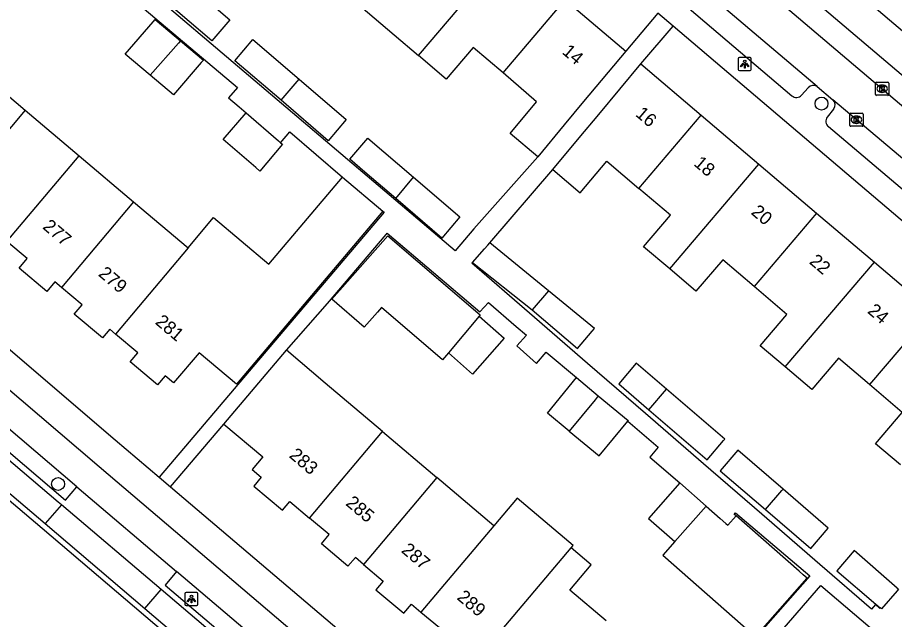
# Model space of a CAD drawing. Extents: x 162532 to 163264, y 381233 to 382042.
# Drawn here: x 162789.7 to 162856.2, y 381584 to 381629.7 of the extents above; entities that cross this region are included whole.
import ezdxf

# ---------------------------------------------------------------- set-up
doc = ezdxf.new("R2010")
doc.units = 0
for name, color, linetype in [('IMGEO_Berm_open', 7, 'Continuous'), ('IMGEO_Boom', 7, 'Continuous'), ('IMGEO_Fietspad_gesloten', 7, 'Continuous'), ('IMGEO_Kolk', 7, 'Continuous'), ('IMGEO_Lichtpunt', 7, 'Continuous'), ('IMGEO_Pand', 7, 'Continuous'), ('IMGEO_Pand_nummerreeks', 7, 'Continuous'), ('IMGEO_Parkeervlak_open', 7, 'Continuous'), ('IMGEO_Rijbaan_lokaal_gesloten', 7, 'Continuous'), ('IMGEO_Rijbaan_lokaal_open', 7, 'Continuous'), ('IMGEO_Voetpad_open', 7, 'Continuous')]:
    doc.layers.add(name, color=color, linetype=linetype)

msp = doc.modelspace()

# ---------------------------------------------------------------- linework, layer by layer
at = {"layer": 'IMGEO_Berm_open'}
for points in [[(162786.69, 381600.434), (162785.841, 381599.426), (162793.281, 381593.086), (162794.151, 381594.096)], [(162800.545, 381586.298), (162792.987, 381592.725)], [(162801.723, 381587.664), (162800.86, 381586.645), (162808.724, 381579.951), (162809.609, 381580.965)]]:
    msp.add_lwpolyline(points, dxfattribs=at)
at = {"layer": 'IMGEO_Boom'}
for centre in [(162850.632, 381623.161), (162792.731, 381594.303)]:
    msp.add_circle(centre, 0.489, dxfattribs=at)
at = {"layer": 'IMGEO_Fietspad_gesloten'}
for points in [[(162862.139, 381539.717), (162835.26, 381562.126), (162827.852, 381568.349), (162795.857, 381595.619), (162764.671, 381622.232), (162735.085, 381647.652), (162710.008, 381669.138)], [(162794.151, 381594.096), (162786.69, 381600.434)], [(162794.151, 381594.096), (162801.723, 381587.664)], [(162809.609, 381580.965), (162801.723, 381587.664)]]:
    msp.add_lwpolyline(points, dxfattribs=at)
at = {"layer": 'IMGEO_Kolk'}
for p, q in [((162854.728, 381623.861), (162854.728, 381624.713)), ((162854.803, 381624.787), (162855.655, 381624.787)), ((162855.216, 381624.567), (162855.241, 381624.567)), ((162855.729, 381624.713), (162855.729, 381623.861)), ((162855.655, 381623.787), (162854.803, 381623.787)), ((162855.239, 381624.007), (162855.214, 381624.007)), ((162852.777, 381621.51), (162852.777, 381622.362)), ((162852.852, 381622.436), (162853.704, 381622.436)), ((162853.265, 381622.216), (162853.29, 381622.216)), ((162853.778, 381622.362), (162853.778, 381621.51)), ((162853.288, 381621.656), (162853.263, 381621.656)), ((162853.704, 381621.436), (162852.852, 381621.436))]:
    msp.add_line(p, q, dxfattribs=at)
for points in [[(162854.728, 381623.861), (162854.728, 381624.713)], [(162854.803, 381624.787), (162855.655, 381624.787)], [(162855.049, 381624.487), (162855.172, 381624.487), (162855.172, 381624.336), (162855.302, 381624.487), (162855.466, 381624.487), (162855.32, 381624.336), (162855.473, 381624.087), (162855.321, 381624.087), (162855.236, 381624.251), (162855.172, 381624.184), (162855.172, 381624.087), (162855.049, 381624.087), (162855.049, 381624.487)], [(162855.729, 381624.713), (162855.729, 381623.861)], [(162855.655, 381623.787), (162854.803, 381623.787)], [(162852.777, 381621.51), (162852.777, 381622.362)], [(162852.852, 381622.436), (162853.704, 381622.436)], [(162853.778, 381622.362), (162853.778, 381621.51)], [(162853.098, 381622.136), (162853.221, 381622.136), (162853.221, 381621.985), (162853.351, 381622.136), (162853.515, 381622.136), (162853.369, 381621.985), (162853.522, 381621.736), (162853.37, 381621.736), (162853.285, 381621.9), (162853.221, 381621.833), (162853.221, 381621.736), (162853.098, 381621.736), (162853.098, 381622.136)], [(162853.704, 381621.436), (162852.852, 381621.436)]]:
    msp.add_lwpolyline(points, dxfattribs=at)
for centre, start, end in [((162854.805, 381624.711), 91.55205, 178.44795), ((162854.805, 381624.711), 91.55205, 178.44795), ((162855.653, 381624.711), 1.55205, 88.44795), ((162855.653, 381624.711), 1.55205, 88.44795), ((162854.805, 381623.863), 181.55205, 268.44795), ((162854.805, 381623.863), 181.55205, 268.44795), ((162855.653, 381623.863), 271.55205, 358.44795), ((162855.653, 381623.863), 271.55205, 358.44795), ((162852.854, 381622.36), 91.55205, 178.44795), ((162852.854, 381622.36), 91.55205, 178.44795), ((162853.702, 381622.36), 1.55205, 88.44795), ((162853.702, 381622.36), 1.55205, 88.44795), ((162852.854, 381621.512), 181.55205, 268.44795), ((162852.854, 381621.512), 181.55205, 268.44795), ((162853.702, 381621.512), 271.55205, 358.44795), ((162853.702, 381621.512), 271.55205, 358.44795)]:
    msp.add_arc(centre, 0.0765, start, end, dxfattribs=at)
for centre, major_axis, ratio, start_param, end_param in [((162855.215, 381624.287), (-0.387, 0.002), 0.722429, 4.712389, 7.853982), ((162855.24, 381624.287), (-0.39, 0.002), 0.717154, 1.570796, 4.712389), ((162853.264, 381621.936), (-0.387, 0.002), 0.722429, 4.712389, 7.853982), ((162853.289, 381621.936), (-0.39, 0.002), 0.717154, 1.570796, 4.712389)]:
    msp.add_ellipse(centre, major_axis=major_axis, ratio=ratio, start_param=start_param, end_param=end_param, dxfattribs=at)
at = {"layer": 'IMGEO_Lichtpunt'}
for p, q in [((162844.309, 381626.565), (162844.309, 381625.758)), ((162844.309, 381626.565), (162844.309, 381625.758)), ((162845.211, 381626.66), (162844.403, 381626.66)), ((162845.211, 381626.66), (162844.403, 381626.66)), ((162845.305, 381625.758), (162845.305, 381626.565)), ((162845.305, 381625.758), (162845.305, 381626.565)), ((162844.403, 381625.664), (162845.211, 381625.664)), ((162844.403, 381625.664), (162845.211, 381625.664)), ((162802.344, 381585.986), (162802.344, 381585.179)), ((162802.344, 381585.986), (162802.344, 381585.179)), ((162803.246, 381586.081), (162802.438, 381586.081)), ((162803.246, 381586.081), (162802.438, 381586.081)), ((162803.34, 381585.179), (162803.34, 381585.986)), ((162803.34, 381585.179), (162803.34, 381585.986)), ((162802.438, 381585.085), (162803.246, 381585.085)), ((162802.438, 381585.085), (162803.246, 381585.085))]:
    msp.add_line(p, q, dxfattribs=at)
for points in [[(162844.683, 381626.229), (162844.722, 381626.201), (162844.534, 381625.939), (162844.496, 381625.966), (162844.683, 381626.229)], [(162844.785, 381626.181), (162844.832, 381626.181), (162844.832, 381625.859), (162844.785, 381625.859), (162844.785, 381626.181)], [(162844.895, 381626.201), (162844.933, 381626.228), (162845.12, 381625.966), (162845.081, 381625.938), (162844.895, 381626.201)], [(162802.718, 381585.65), (162802.757, 381585.622), (162802.569, 381585.36), (162802.531, 381585.387), (162802.718, 381585.65)], [(162802.82, 381585.602), (162802.867, 381585.602), (162802.867, 381585.28), (162802.82, 381585.28), (162802.82, 381585.602)], [(162802.93, 381585.622), (162802.968, 381585.649), (162803.155, 381585.387), (162803.116, 381585.359), (162802.93, 381585.622)]]:
    msp.add_lwpolyline(points, dxfattribs=at)
for centre in [(162844.808, 381626.363), (162802.843, 381585.784)]:
    msp.add_circle(centre, 0.0994, dxfattribs=at)
for centre, start, end in [((162844.403, 381626.565), 90, 180), ((162844.403, 381626.565), 90, 180), ((162845.211, 381626.565), 0, 90), ((162845.211, 381626.565), 0, 90), ((162844.403, 381625.758), 180, 270), ((162844.403, 381625.758), 180, 270), ((162845.211, 381625.758), 270, 0), ((162845.211, 381625.758), 270, 360), ((162802.438, 381585.986), 90, 180), ((162802.438, 381585.986), 90, 180), ((162803.246, 381585.986), 0, 90), ((162803.246, 381585.986), 0, 90), ((162802.438, 381585.179), 180, 270), ((162802.438, 381585.179), 180, 270), ((162803.246, 381585.179), 270, 0), ((162803.246, 381585.179), 270, 360)]:
    msp.add_arc(centre, 0.0946, start, end, dxfattribs=at)
at = {"layer": 'IMGEO_Pand'}
for points in [[(162820.066, 381626.801), (162826.824, 381634.758)], [(162817.732, 381632.92), (162815.691, 381630.516), (162818.218, 381628.37), (162820.066, 381626.801)], [(162802.311, 381632.459), (162805.744, 381629.519), (162804.383, 381627.917), (162800.951, 381630.857)], [(162826.477, 381625.484), (162831.199, 381631.044)], [(162831.199, 381631.044), (162835.786, 381627.149)], [(162799.713, 381625.317), (162797.828, 381626.913), (162799.948, 381629.362), (162800.104, 381629.542), (162802.013, 381627.927)], [(162802.013, 381627.927), (162803.75, 381626.455), (162803.593, 381626.274), (162801.473, 381623.826), (162799.713, 381625.317)], [(162802.013, 381627.927), (162801.855, 381627.747), (162799.713, 381625.317)], [(162809.644, 381623.41), (162806.14, 381626.412), (162807.501, 381628.014), (162811.005, 381625.012)], [(162826.477, 381625.484), (162824.213, 381627.409), (162822.173, 381625.011), (162820.066, 381626.801)], [(162835.786, 381627.149), (162832.587, 381623.307), (162831.115, 381621.54), (162829.104, 381619.127)], [(162785.966, 381626.265), (162790.244, 381622.649)], [(162830.245, 381618.158), (162832.258, 381620.568), (162833.733, 381622.334), (162836.937, 381626.171)], [(162836.937, 381626.171), (162841.51, 381622.288)], [(162811.005, 381625.012), (162814.582, 381621.949), (162813.221, 381620.346), (162809.644, 381623.41)], [(162809.644, 381623.41), (162811.005, 381625.012)], [(162829.104, 381619.127), (162827.023, 381620.893), (162829.017, 381623.287), (162826.477, 381625.484)], [(162790.244, 381622.649), (162784.77, 381616.159)], [(162790.244, 381622.649), (162794.326, 381619.198)], [(162809.611, 381620.196), (162809.743, 381620.082), (162808.024, 381618.045), (162807.723, 381618.304), (162805.247, 381620.431), (162806.984, 381622.453)], [(162806.984, 381622.453), (162809.442, 381620.341), (162809.611, 381620.196)], [(162836.783, 381616.721), (162841.51, 381622.288)], [(162841.51, 381622.288), (162845.886, 381618.573)], [(162818.337, 381615.964), (162816.003, 381617.964), (162814.865, 381618.938), (162816.225, 381620.541), (162819.698, 381617.567)], [(162788.85, 381612.707), (162794.326, 381619.198)], [(162794.326, 381619.198), (162798.458, 381615.705)], [(162830.245, 381618.158), (162832.326, 381616.391), (162834.338, 381618.799), (162836.783, 381616.721)], [(162839.128, 381610.615), (162845.886, 381618.573)], [(162845.886, 381618.573), (162850.262, 381614.857)], [(162802.586, 381612.214), (162804.529, 381614.515), (162808.708, 381610.98), (162814.297, 381617.588)], [(162814.297, 381617.588), (162817.355, 381615.001)], [(162819.698, 381617.567), (162823.208, 381614.561), (162821.84, 381612.964), (162818.337, 381615.964)], [(162818.337, 381615.964), (162819.698, 381617.567)], [(162839.128, 381610.615), (162837.14, 381612.303), (162839.17, 381614.691), (162836.783, 381616.721)], [(162798.458, 381615.705), (162792.985, 381609.217)], [(162798.458, 381615.705), (162802.586, 381612.214)], [(162817.355, 381615.001), (162806.25, 381601.871), (162803.425, 381604.261), (162801.488, 381601.97), (162800.852, 381602.508), (162800.272, 381601.822), (162798.206, 381603.569), (162798.776, 381604.243), (162797.075, 381605.681)], [(162850.262, 381614.857), (162845.529, 381609.284)], [(162850.262, 381614.857), (162854.637, 381611.143)], [(162822.339, 381604.26), (162821.89, 381603.723), (162817.257, 381607.69), (162816.948, 381607.34), (162815.955, 381606.211), (162813.492, 381608.319), (162813.667, 381608.517), (162814.31, 381609.248), (162817.732, 381613.137), (162824.744, 381607.132), (162824.664, 381607.037)], [(162792.985, 381609.217), (162792.491, 381609.635), (162791.875, 381608.906), (162789.781, 381610.676), (162790.395, 381611.401), (162788.85, 381612.707)], [(162802.586, 381612.214), (162797.075, 381605.681)], [(162824.171, 381611.101), (162825.064, 381612.132), (162825.32, 381612.427), (162825.477, 381612.609)], [(162829.919, 381608.965), (162825.477, 381612.609)], [(162824.171, 381611.101), (162828.689, 381607.517)], [(162845.529, 381609.284), (162843.137, 381611.317), (162841.11, 381608.932), (162839.128, 381610.615)], [(162847.879, 381603.185), (162854.637, 381611.143)], [(162854.637, 381611.143), (162859.013, 381607.427)], [(162797.075, 381605.681), (162796.646, 381606.043), (162796.091, 381605.386), (162793.961, 381607.187), (162794.555, 381607.89), (162792.985, 381609.217)], [(162829.919, 381608.965), (162828.689, 381607.517)], [(162828.689, 381607.517), (162832.121, 381604.578), (162833.246, 381605.903), (162833.413, 381606.099), (162829.919, 381608.965)], [(162847.879, 381603.185), (162845.984, 381604.794), (162848.008, 381607.175), (162845.529, 381609.284)], [(162824.664, 381607.037), (162826.561, 381605.367), (162824.169, 381602.649), (162822.339, 381604.26)], [(162824.664, 381607.037), (162822.339, 381604.26)], [(162859.013, 381607.427), (162854.274, 381601.847)], [(162805.308, 381598.846), (162810.043, 381604.446)], [(162817.334, 381598.279), (162812.974, 381601.967), (162810.043, 381604.446)], [(162854.274, 381601.847), (162851.91, 381603.857), (162849.888, 381601.48), (162847.879, 381603.185)], [(162838.864, 381601.503), (162836.574, 381603.465), (162835.247, 381601.901), (162837.537, 381599.939)], [(162831.496, 381598.314), (162829.837, 381599.681), (162832.055, 381602.373)], [(162832.055, 381602.373), (162833.701, 381600.99)], [(162856.631, 381595.754), (162854.737, 381597.362), (162856.756, 381599.736), (162854.274, 381601.847)], [(162833.701, 381600.99), (162833.462, 381600.7), (162831.496, 381598.314)], [(162833.701, 381600.99), (162835.973, 381599.118), (162835.937, 381599.075)], [(162837.537, 381599.939), (162838.864, 381601.503)], [(162837.537, 381599.939), (162841.961, 381596.15), (162843.207, 381597.617), (162843.289, 381597.713), (162838.864, 381601.503)], [(162831.496, 381598.314), (162833.768, 381596.442), (162835.937, 381599.075)], [(162805.308, 381598.846), (162808.248, 381596.361), (162807.441, 381595.406), (162808.135, 381594.819), (162807.572, 381594.153), (162809.749, 381592.312), (162810.312, 381592.978), (162811.793, 381591.726)], [(162811.793, 381591.726), (162817.334, 381598.279)], [(162817.334, 381598.279), (162821.454, 381594.795)], [(162847.717, 381593.92), (162844.279, 381596.865), (162842.951, 381595.302), (162846.384, 381592.361)], [(162821.454, 381594.795), (162815.887, 381588.212)], [(162825.781, 381591.136), (162821.454, 381594.795)], [(162839.883, 381594.386), (162837.521, 381591.701), (162839.518, 381589.945)], [(162839.883, 381594.386), (162841.88, 381592.63)], [(162846.384, 381592.361), (162847.61, 381593.804), (162847.717, 381593.92)], [(162846.384, 381592.361), (162849.814, 381589.423), (162851.126, 381590.967), (162847.717, 381593.92)], [(162831.64, 381589.455), (162831.789, 381589.631), (162827.545, 381593.221), (162825.781, 381591.136)], [(162839.518, 381589.945), (162841.88, 381592.63)], [(162841.88, 381592.63), (162842.948, 381591.691), (162843.385, 381591.307), (162843.538, 381591.172), (162844.16, 381591.88)], [(162815.887, 381588.212), (162815.275, 381588.73), (162814.716, 381588.069), (162812.7, 381589.773), (162813.285, 381590.464), (162811.793, 381591.726)], [(162839.518, 381589.945), (162838.604, 381588.906), (162845.333, 381582.987), (162845.635, 381582.721), (162849.534, 381587.153), (162849.231, 381587.419), (162848.925, 381587.688), (162844.16, 381591.88)], [(162825.781, 381591.136), (162820.251, 381584.594)], [(162824.477, 381580.983), (162831.64, 381589.455)], [(162834.306, 381583.926), (162831.553, 381586.254), (162833.167, 381588.163), (162831.64, 381589.455)], [(162856.377, 381586.417), (162853.107, 381589.251), (162851.804, 381587.718), (162854.752, 381585.194), (162855.091, 381584.903)], [(162815.887, 381588.212), (162817.39, 381586.941), (162816.838, 381586.289), (162818.953, 381584.501), (162819.54, 381585.195), (162820.251, 381584.594)], [(162856.377, 381586.417), (162856.48, 381586.328), (162856.378, 381586.21), (162855.18, 381584.827), (162855.091, 381584.903)], [(162820.251, 381584.594), (162821.65, 381583.412), (162821.051, 381582.703), (162823.188, 381580.896), (162823.768, 381581.582), (162824.477, 381580.983)]]:
    msp.add_lwpolyline(points, dxfattribs=at)
at = {"layer": 'IMGEO_Parkeervlak_open'}
for points in [[(162792.987, 381592.725), (162792.734, 381592.94), (162768.464, 381613.585)], [(162792.987, 381592.725), (162791.759, 381591.313)], [(162799.313, 381584.87), (162800.545, 381586.298)], [(162825.096, 381565.419), (162800.545, 381586.298)]]:
    msp.add_lwpolyline(points, dxfattribs=at)
at = {"layer": 'IMGEO_Rijbaan_lokaal_gesloten'}
msp.add_lwpolyline([(162838.874, 381550.696), (162834.758, 381554.093), (162791.516, 381590.924), (162760.162, 381617.53), (162731.009, 381642.342), (162708.69, 381661.323)], dxfattribs=at)
at = {"layer": 'IMGEO_Rijbaan_lokaal_open'}
for points in [[(162826.092, 381649.024), (162869.033, 381612.565)], [(162850.293, 381624.446), (162832.662, 381639.429)], [(162850.293, 381624.446), (162851.487, 381623.45)], [(162858.86, 381617.221), (162851.487, 381623.45)], [(162767.29, 381612.096), (162791.759, 381591.313)], [(162791.759, 381591.313), (162799.313, 381584.87)], [(162799.313, 381584.87), (162823.839, 381563.975)]]:
    msp.add_lwpolyline(points, dxfattribs=at)
at = {"layer": 'IMGEO_Voetpad_open'}
for points in [[(162812.522, 381662.862), (162826.436, 381651.063), (162871.782, 381612.563), (162893.937, 381593.76)], [(162738.266, 381648.058), (162797.068, 381597.652), (162800.385, 381594.834)], [(162829.104, 381619.127), (162824.272, 381613.649), (162822.847, 381611.985), (162796.51, 381634.375), (162792.035, 381638.152), (162792.178, 381638.353)], [(162832.302, 381637.458), (162848.392, 381623.761)], [(162889.33, 381605.035), (162887.391, 381602.747), (162852.007, 381632.723)], [(162795.6, 381632.007), (162797.098, 381630.737), (162797.82, 381631.588), (162806.325, 381624.38), (162805.66, 381623.595), (162806.456, 381622.906), (162806.984, 381622.453)], [(162838.227, 381630.019), (162835.786, 381627.149)], [(162839.377, 381629.041), (162838.227, 381630.019)], [(162836.937, 381626.171), (162839.377, 381629.041)], [(162870.268, 381602.775), (162839.377, 381629.041)], [(162849.116, 381623.787), (162849.618, 381624.365)], [(162851.547, 381622.742), (162851.063, 381622.131)], [(162809.611, 381620.196), (162810.306, 381621.007), (162814.297, 381617.588)], [(162851.167, 381621.412), (162856.918, 381616.538)], [(162825.477, 381612.609), (162830.245, 381618.158)], [(162817.355, 381615.001), (162817.45, 381614.92), (162800.385, 381594.834)], [(162810.043, 381604.446), (162813.17, 381607.999), (162817.619, 381613.236), (162817.694, 381613.324), (162824.715, 381607.358), (162825.364, 381608.079), (162827.465, 381606.264), (162828.245, 381605.589), (162827.53, 381604.795), (162829.016, 381603.457), (162829.757, 381604.305), (162832.055, 381602.373)], [(162855.091, 381584.903), (162855.059, 381584.865), (162854.718, 381585.155), (162854.417, 381584.807), (162850.495, 381588.204), (162846.092, 381592.017), (162841.689, 381595.83), (162837.286, 381599.644), (162832.883, 381603.457), (162828.48, 381607.271), (162824.122, 381611.046), (162824.171, 381611.101)], [(162835.937, 381599.075), (162838.252, 381597.092), (162837.599, 381596.338), (162839.883, 381594.386)], [(162801.265, 381594.087), (162805.308, 381598.846)], [(162800.385, 381594.834), (162801.265, 381594.087)], [(162801.265, 381594.087), (162832.233, 381567.778), (162832.354, 381568.007), (162832.559, 381567.833)], [(162844.16, 381591.88), (162844.018, 381592.005), (162844.114, 381592.114), (162849.735, 381587.341), (162832.559, 381567.833)], [(162845.02, 381580.183), (162850.589, 381586.613), (162857.375, 381580.825), (162858.193, 381581.784)]]:
    msp.add_lwpolyline(points, dxfattribs=at)
for centre, radius, start, end in [((162849.997, 381624.06), 0.486, 52.51008, 141.17547), ((162848.741, 381624.136), 0.512, 227.04563, 317.06777), ((162851.15, 381623.065), 0.512, 320.85381, 48.83419), ((162851.454, 381621.821), 0.5, 141.58043, 234.88053)]:
    msp.add_arc(centre, radius, start, end, dxfattribs=at)

# ---------------------------------------------------------------- texts
at = {"layer": 'IMGEO_Pand_nummerreeks'}
for s, rotation, p in [('14', 319.66791, (162830.894, 381626.999)), ('16', 319.66674, (162836.461, 381622.272)), ('18', 319.66674, (162840.88, 381618.52)), ('20', 319.66674, (162845.226, 381614.829)), ('277', 319.76688, (162791.496, 381613.724)), ('22', 319.66674, (162849.639, 381611.084)), ('279', 319.76688, (162795.723, 381610.148)), ('24', 319.66674, (162854.057, 381607.332)), ('281', 319.7669, (162800.036, 381606.499)), ('283', 319.77985, (162810.192, 381596.38)), ('285', 319.74971, (162814.48, 381592.754)), ('287', 319.74971, (162818.7, 381589.181)), ('289', 319.74971, (162822.92, 381585.609))]:
    msp.add_text(s, height=1, rotation=rotation, dxfattribs=at).set_placement(p)

doc.saveas('drawing.dxf')
